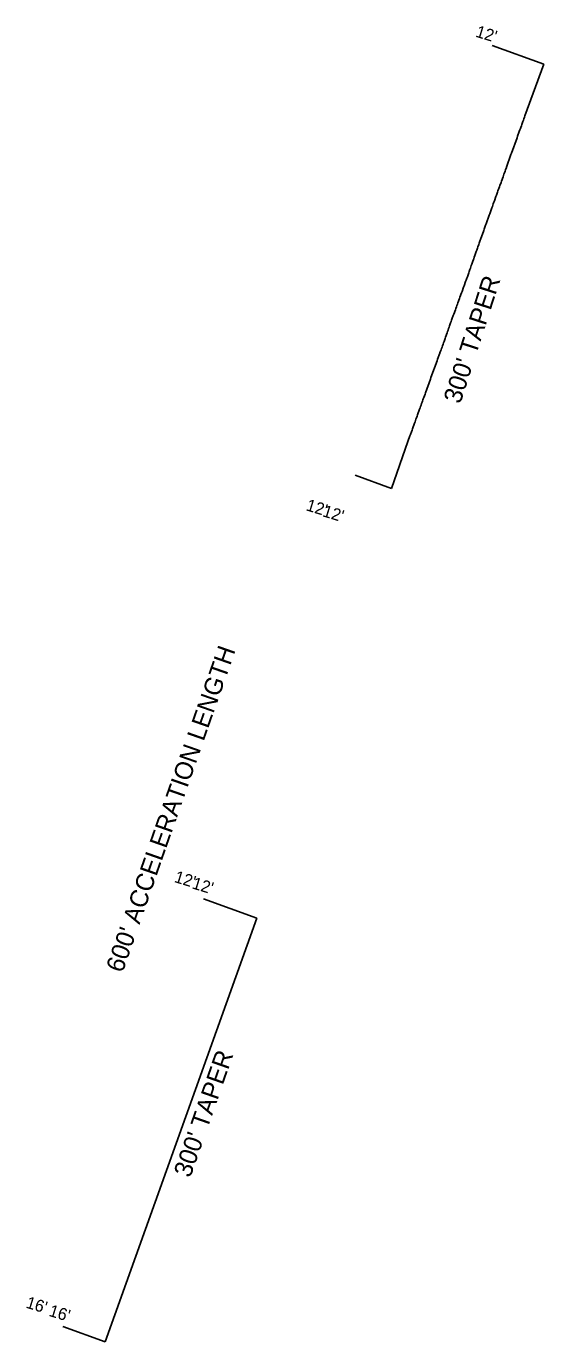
# Model space of a CAD drawing. Extents: x 1938363 to 1944069, y 778949 to 784066.
# Drawn here: x 1941430 to 1941775, y 781769 to 782645 of the extents above; entities that cross this region are included whole.
import ezdxf

# ---------------------------------------------------------------- set-up
doc = ezdxf.new("R2010")
doc.units = 0
doc.layers.add('RD_PD_Final_TX', color=7, linetype='Continuous')

msp = doc.modelspace()

# ---------------------------------------------------------------- linework, layer by layer
at = {"layer": 'RD_PD_Final_TX'}
for p, q in [((1941740.43, 782632.58), (1941774.89, 782620.23)), ((1941649.09, 782346.17), (1941673.41, 782337.37)), ((1941547.93, 782063.78), (1941583.66, 782050.85)), ((1941583.66, 782050.85), (1941482.53, 781768.54)), ((1941454.29, 781778.65), (1941482.53, 781768.54))]:
    msp.add_line(p, q, dxfattribs=at)
msp.add_lwpolyline([(1941774.89, 782620.23), (1941762.39, 782585.67), (1941762.06, 782584.73), (1941761.67, 782583.64), (1941761.41, 782582.91), (1941761.05, 782581.9), (1941760.37, 782580.02), (1941760.04, 782579.08), (1941759.65, 782577.99), (1941759.39, 782577.26), (1941759.05, 782576.31), (1941758.64, 782575.17), (1941757.52, 782572.06), (1941757.17, 782571.12), (1941753.43, 782560.78), (1941753.08, 782559.84), (1941750.05, 782551.46), (1941749.98, 782551.27), (1941749.43, 782549.76), (1941749.1, 782548.82), (1941748.71, 782547.73), (1941748.37, 782546.78), (1941748.08, 782545.99), (1941747.75, 782545.05), (1941746.73, 782542.23), (1941746.43, 782541.36), (1941746.01, 782540.19), (1941745.72, 782539.4), (1941745.39, 782538.46), (1941744.37, 782535.64), (1941744.07, 782534.77), (1941743.65, 782533.6), (1941743.36, 782532.81), (1941743.03, 782531.87), (1941742.01, 782529.05), (1941741.71, 782528.18), (1941741.29, 782527.01), (1941740.66, 782525.28), (1941740.33, 782524.34), (1941739.89, 782523.13), (1941739.85, 782523.02), (1941738.93, 782520.47), (1941738.6, 782519.53), (1941736.51, 782513.74), (1941736.17, 782512.79), (1941735.2, 782510.12), (1941734.87, 782509.18), (1941732.77, 782503.37), (1941732.57, 782502.81), (1941731.92, 782500.95), (1941731.58, 782500), (1941730.99, 782498.35), (1941730.66, 782497.4), (1941730.23, 782496.16), (1941729.92, 782495.29), (1941729.66, 782494.57), (1941729, 782492.69), (1941728.6, 782491.51), (1941728.23, 782490.5), (1941728, 782489.86), (1941727.67, 782488.91), (1941726.94, 782486.8), (1941726.6, 782485.85), (1941726.01, 782484.2), (1941725.68, 782483.25), (1941725.25, 782482.01), (1941724.94, 782481.14), (1941724.68, 782480.42), (1941723.98, 782478.42), (1941723.66, 782477.52), (1941723.18, 782476.17), (1941722.83, 782475.23), (1941721.81, 782472.41), (1941721.46, 782471.47), (1941720.44, 782468.65), (1941720.09, 782467.71), (1941719.07, 782464.89), (1941718.72, 782463.95), (1941717.7, 782461.13), (1941717.35, 782460.19), (1941717.06, 782459.39), (1941716.72, 782458.46), (1941716.33, 782457.38), (1941715.98, 782456.44), (1941714.96, 782453.62), (1941714.61, 782452.68), (1941713.95, 782450.87), (1941713.73, 782450.25), (1941713.45, 782449.47), (1941713.14, 782448.6), (1941712.81, 782447.65), (1941712.1, 782445.7), (1941711.77, 782444.76), (1941711.46, 782443.89), (1941711.13, 782442.94), (1941710.76, 782441.93), (1941710.43, 782440.99), (1941710.09, 782440.05), (1941709.79, 782439.18), (1941709.45, 782438.23), (1941709.09, 782437.22), (1941708.41, 782435.34), (1941708.11, 782434.47), (1941707.77, 782433.52), (1941707.41, 782432.51), (1941707.07, 782431.57), (1941706.77, 782430.7), (1941706.43, 782429.75), (1941706.07, 782428.74), (1941705.68, 782427.67), (1941705.63, 782427.51), (1941704.16, 782423.43), (1941703.81, 782422.49), (1941699.73, 782411.21), (1941699.38, 782410.27), (1941696.09, 782401.17), (1941695.75, 782400.22), (1941694.96, 782398.04), (1941694.61, 782397.1), (1941694.33, 782396.34), (1941694.05, 782395.57), (1941693.81, 782394.9), (1941693.48, 782393.96), (1941693.09, 782392.87), (1941692.75, 782391.92), (1941692.46, 782391.13), (1941692.13, 782390.19), (1941690.77, 782386.43), (1941690.44, 782385.49), (1941690.05, 782384.4), (1941689.71, 782383.45), (1941689.08, 782381.72), (1941688.75, 782380.78), (1941687.39, 782377.02), (1941687.09, 782376.15), (1941686.67, 782374.98), (1941686.04, 782373.25), (1941685.71, 782372.31), (1941684.35, 782368.55), (1941673.41, 782337.37)], dxfattribs=at)

# ---------------------------------------------------------------- texts
for s, height, rotation, p in [("12'", 8, 343.00992, (1941728.97, 782638.56)), ("300' TAPER", 12, 72.06711, (1941719.2, 782393.19)), ("12'", 8, 343.00992, (1941615.87, 782322.85)), ("12'", 8, 343.00992, (1941626.87, 782318.9)), ("600' ACCELERATION LENGTH", 12, 70.6954, (1941493.98, 782013.92)), ("12'", 8, 343.00992, (1941528.02, 782075.06)), ("12'", 8, 343.00992, (1941539.86, 782070.82)), ("300' TAPER", 12, 70.6954, (1941539.15, 781877.33)), ("16'", 8, 343.00992, (1941429.05, 781791.33)), ("16'", 8, 343.00992, (1941444.35, 781785.85))]:
    msp.add_text(s, height=height, rotation=rotation, dxfattribs=at).set_placement(p)

doc.saveas('drawing.dxf')
